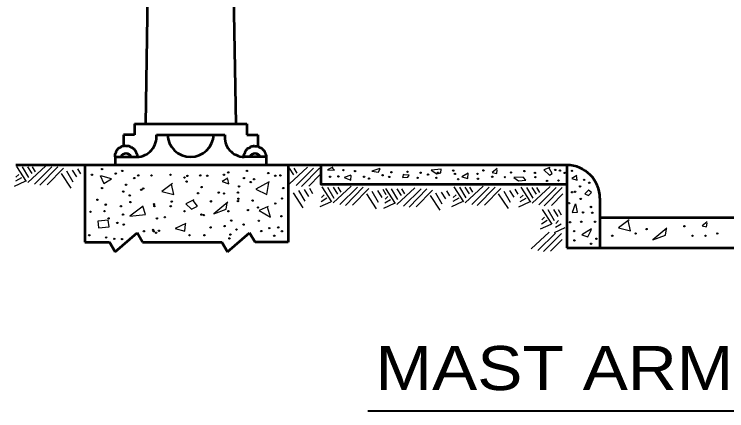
# Model space of a CAD drawing. Extents: x -370 to 486, y -203 to 341.
# Drawn here: x -36.8 to 40.8, y 133.8 to 177 of the extents above; entities that cross this region are included whole.
import ezdxf
from ezdxf.enums import TextEntityAlignment as Align

# ---------------------------------------------------------------- set-up
doc = ezdxf.new("R2010")
doc.units = 0
doc.header["$LTSCALE"] = 0.96
doc.layers.add('1', color=7, linetype='Continuous', lineweight=53)

msp = doc.modelspace()

# ---------------------------------------------------------------- hatches: boundary and pattern name
at = {"layer": '1'}
for points in [[(-27.1974, 160.0917, 1), (-27.3438, 160.0917, 1)], [(-24.9998, 159.8848, 1), (-25.1462, 159.8848, 1)], [(-11.4259, 159.8848, 1), (-11.5723, 159.8848, 1)], [(-0.9302, 159.9722, 1), (-1.0766, 159.9722, 1)], [(0.3404, 159.8705, 1), (0.194, 159.8705, 1)], [(6.058, 159.7943, 1), (5.9116, 159.7943, 1)], [(11.0387, 159.9214, 1), (10.8923, 159.9214, 1)], [(14.3167, 159.9468, 1), (14.1703, 159.9468, 1)], [(18.7892, 159.8705, 1), (18.6428, 159.8705, 1)], [(22.1435, 159.9976, 1), (21.9971, 159.9976, 1)], [(22.6517, 159.9214, 1), (22.5053, 159.9214, 1)], [(23.9764, 159.898, 1), (23.83, 159.898, 1)], [(-28.3092, 159.4709, 1), (-28.4556, 159.4709, 1)], [(-25.7237, 159.6003, 1), (-25.8701, 159.6003, 1)], [(-23.707, 159.1089, 1), (-23.8534, 159.1089, 1)], [(-23.2675, 159.3934, 1), (-23.4139, 159.3934, 1)], [(-21.8196, 159.3934, 1), (-21.966, 159.3934, 1)], [(-19.7512, 159.4709, 1), (-19.8976, 159.4709, 1)], [(-18.2257, 159.1606, 1), (-18.3721, 159.1606, 1)], [(-17.9155, 159.3416, 1), (-18.0619, 159.3416, 1)], [(-16.5193, 159.3934, 1), (-16.6657, 159.3934, 1)], [(-15.7437, 159.3675, 1), (-15.8901, 159.3675, 1)], [(-13.9338, 159.4709, 1), (-14.0802, 159.4709, 1)], [(-13.4684, 159.7296, 1), (-13.6148, 159.7296, 1)], [(-11.762, 159.1089, 1), (-11.9084, 159.1089, 1)], [(-9.0989, 159.652, 1), (-9.2453, 159.652, 1)], [(-8.3491, 159.3675, 1), (-8.4955, 159.3675, 1)], [(-7.7803, 159.3934, 1), (-7.9267, 159.3934, 1)], [(-2.3786, 159.2605, 1), (-2.525, 159.2605, 1)], [(-1.4638, 159.2859, 1), (-1.6102, 159.2859, 1)], [(1.3315, 159.2605, 1), (1.1851, 159.2605, 1)], [(1.8651, 159.0571, 1), (1.7187, 159.0571, 1)], [(3.339, 159.413, 1), (3.1926, 159.413, 1)], [(4.0759, 159.235, 1), (3.9295, 159.235, 1)], [(4.3046, 159.7434, 1), (4.1582, 159.7434, 1)], [(7.1507, 159.1334, 1), (7.0043, 159.1334, 1)], [(7.481, 159.6926, 1), (7.3346, 159.6926, 1)], [(8.2942, 159.4892, 1), (8.1478, 159.4892, 1)], [(9.209, 159.1334, 1), (9.0626, 159.1334, 1)], [(9.3869, 159.6926, 1), (9.2405, 159.6926, 1)], [(11.2165, 159.5655, 1), (11.0701, 159.5655, 1)], [(13.6815, 159.5655, 1), (13.5351, 159.5655, 1)], [(13.7323, 159.0317, 1), (13.5859, 159.0317, 1)], [(15.2824, 159.2605, 1), (15.136, 159.2605, 1)], [(16.6546, 159.2096, 1), (16.5082, 159.2096, 1)], [(17.3153, 159.718, 1), (17.1689, 159.718, 1)], [(19.9327, 159.6672, 1), (19.7863, 159.6672, 1)], [(19.9835, 159.2096, 1), (19.8371, 159.2096, 1)], [(23.1854, 159.6672, 1), (23.039, 159.6672, 1)], [(-24.5861, 158.3847, 1), (-24.7325, 158.3847, 1)], [(-17.993, 158.7209, 1), (-18.1394, 158.7209, 1)], [(-11.0122, 158.6692, 1), (-11.1586, 158.6692, 1)], [(-10.6502, 158.9795, 1), (-10.7966, 158.9795, 1)], [(11.5723, 158.9808, 1), (11.4259, 158.9808, 1)], [(21.2541, 158.8029, 1), (21.1077, 158.8029, 1)], [(22.4992, 158.8283, 1), (22.3528, 158.8283, 1)], [(25.2948, 158.9089, 1), (25.1484, 158.9089, 1)], [(25.8551, 158.5957, 1), (25.7087, 158.5957, 1)], [(-27.1974, 158.0226, 1), (-27.3438, 158.0226, 1)], [(-24.8963, 157.6347, 1), (-25.0427, 157.6347, 1)], [(-22.9314, 157.8416, 1), (-23.0778, 157.8416, 1)], [(-22.7245, 157.9709, 1), (-22.8709, 157.9709, 1)], [(-16.752, 157.4536, 1), (-16.8984, 157.4536, 1)], [(-16.3642, 158.1261, 1), (-16.5106, 158.1261, 1)], [(-14.5026, 157.5312, 1), (-14.649, 157.5312, 1)], [(-12.4084, 157.5312, 1), (-12.5548, 157.5312, 1)], [(-12.2791, 158.2036, 1), (-12.4255, 158.2036, 1)], [(-7.4701, 158.0226, 1), (-7.6165, 158.0226, 1)], [(23.9764, 157.5571, 1), (23.83, 157.5571, 1)], [(24.306, 157.6231, 1), (24.1596, 157.6231, 1)], [(24.8498, 158.2, 1), (24.7034, 158.2, 1)], [(-27.7145, 156.7553, 1), (-27.8609, 156.7553, 1)], [(-24.1983, 157.2208, 1), (-24.3447, 157.2208, 1)], [(-13.9338, 157.4277, 1), (-14.0802, 157.4277, 1)], [(-12.3567, 156.8588, 1), (-12.5031, 156.8588, 1)], [(-7.6252, 156.8846, 1), (-7.7716, 156.8846, 1)], [(24.9158, 156.8318, 1), (24.7694, 156.8318, 1)], [(-26.8096, 156.2122, 1), (-26.956, 156.2122, 1)], [(-25.1549, 156.0311, 1), (-25.3013, 156.0311, 1)], [(-24.1207, 156.4967, 1), (-24.2671, 156.4967, 1)], [(-21.561, 156.2639, 1), (-21.7074, 156.2639, 1)], [(-21.5093, 156.057, 1), (-21.6557, 156.057, 1)], [(-19.7253, 156.0311, 1), (-19.8717, 156.0311, 1)], [(-19.6219, 156.5484, 1), (-19.7683, 156.5484, 1)], [(-15.3558, 156.5743, 1), (-15.5022, 156.5743, 1)], [(-12.4084, 156.6001, 1), (-12.5548, 156.6001, 1)], [(-10.8054, 156.6518, 1), (-10.9518, 156.6518, 1)], [(-10.2107, 155.9018, 1), (-10.3571, 155.9018, 1)], [(-8.3491, 156.3415, 1), (-8.4955, 156.3415, 1)], [(23.6633, 156.3702, 1), (23.5169, 156.3702, 1)], [(26.0364, 155.958, 1), (25.89, 155.958, 1)], [(-28.4643, 155.4363, 1), (-28.6107, 155.4363, 1)], [(-26.9389, 155.5139, 1), (-27.0853, 155.5139, 1)], [(-24.9222, 155.1259, 1), (-25.0686, 155.1259, 1)], [(-18.2257, 155.488, 1), (-18.3721, 155.488, 1)], [(-16.39, 155.1259, 1), (-16.5364, 155.1259, 1)], [(-13.4426, 155.488, 1), (-13.589, 155.488, 1)], [(-11.3225, 155.6173, 1), (-11.4689, 155.6173, 1)], [(25.1794, 155.3646, 1), (25.033, 155.3646, 1)], [(26.1847, 155.3316, 1), (26.0383, 155.3316, 1)], [(-26.4993, 154.7121, 1), (-26.6457, 154.7121, 1)], [(-21.2249, 154.7121, 1), (-21.3713, 154.7121, 1)], [(-20.3717, 154.8414, 1), (-20.5181, 154.8414, 1)], [(-16.1315, 155.0742, 1), (-16.2779, 155.0742, 1)], [(-13.1323, 154.4793, 1), (-13.2787, 154.4793, 1)], [(-10.1331, 154.4535, 1), (-10.2795, 154.4535, 1)], [(-7.6769, 154.9449, 1), (-7.8233, 154.9449, 1)], [(24.9817, 154.359, 1), (24.8353, 154.359, 1)], [(26.4813, 154.359, 1), (26.3349, 154.359, 1)], [(-25.5427, 154.2207, 1), (-25.6891, 154.2207, 1)], [(-24.8446, 154.0397, 1), (-24.991, 154.0397, 1)], [(-15.3817, 153.7293, 1), (-15.5281, 153.7293, 1)], [(-13.8562, 153.8845, 1), (-14.0026, 153.8845, 1)], [(-11.7878, 154.0397, 1), (-11.9342, 154.0397, 1)], [(-8.9955, 153.6517, 1), (-9.1419, 153.6517, 1)], [(-8.013, 153.7293, 1), (-8.1594, 153.7293, 1)], [(23.7622, 154.293, 1), (23.6158, 154.293, 1)], [(36.2199, 153.8654, 1), (36.0735, 153.8654, 1)], [(-28.5936, 152.8758, 1), (-28.74, 152.8758, 1)], [(-22.647, 153.3155, 1), (-22.7934, 153.3155, 1)], [(-21.6645, 153.4707, 1), (-21.8109, 153.4707, 1)], [(-21.5869, 153.3155, 1), (-21.7333, 153.3155, 1)], [(-21.3283, 153.1603, 1), (-21.4747, 153.1603, 1)], [(-21.0181, 153.3672, 1), (-21.1645, 153.3672, 1)], [(-17.6828, 152.8758, 1), (-17.8292, 152.8758, 1)], [(-16.0539, 152.8758, 1), (-16.2003, 152.8758, 1)], [(-13.2357, 152.9534, 1), (-13.3821, 152.9534, 1)], [(-12.5635, 153.4965, 1), (-12.7099, 153.4965, 1)], [(-9.8746, 153.3413, 1), (-10.021, 153.3413, 1)], [(-8.4525, 152.8241, 1), (-8.5989, 152.8241, 1)], [(-7.6252, 153.3155, 1), (-7.7716, 153.3155, 1)], [(24.2071, 153.3369, 1), (24.0607, 153.3369, 1)], [(28.3602, 152.833, 1), (28.2138, 152.833, 1)], [(30.9008, 153.0713, 1), (30.7544, 153.0713, 1)], [(32.0916, 153.5478, 1), (31.9452, 153.5478, 1)], [(37.0932, 152.833, 1), (36.9468, 152.833, 1)], [(38.5129, 152.833, 1), (38.3665, 152.833, 1)], [(39.7925, 153.0713, 1), (39.6461, 153.0713, 1)], [(-26.7579, 152.643, 1), (-26.9043, 152.643, 1)], [(-25.8788, 152.4879, 1), (-26.0252, 152.4879, 1)], [(-25.0256, 152.462, 1), (-25.172, 152.462, 1)], [(-13.3391, 152.5396, 1), (-13.4855, 152.5396, 1)], [(24.2401, 152.3148, 1), (24.0937, 152.3148, 1)], [(26.6297, 152.4962, 1), (26.4833, 152.4962, 1)], [(26.0529, 151.9521, 1), (25.9065, 151.9521, 1)]]:
    msp.add_hatch(color=256, dxfattribs=at).paths.add_polyline_path(points)

# ---------------------------------------------------------------- linework, layer by layer
for p, q in [((-20.3421, 292.1994), (-22.562, 165.0188)), ((-14.6437, 275.1007), (-12.7222, 165.0188)), ((-23.762, 165.0188), (-11.5222, 165.0188)), ((-23.762, 165.0188), (-23.762, 163.8188)), ((-11.5222, 165.0188), (-11.5222, 163.8188)), ((-23.762, 163.8188), (-24.962, 163.8188)), ((-24.962, 163.8188), (-24.962, 162.6188)), ((-21.362, 163.8188), (-13.9222, 163.8188)), ((-11.5222, 163.8188), (-10.3222, 163.8188)), ((-10.3222, 163.8188), (-10.3222, 162.572)), ((-25.862, 161.4188), (-25.862, 160.5188)), ((-25.862, 161.4188), (-23.462, 161.4188)), ((-9.4222, 161.4188), (-11.8222, 161.4188)), ((-9.4222, 161.4188), (-9.4222, 160.5188)), ((23.338, 160.5188), (-36.662, 160.5188)), ((-29.162, 160.5188), (-29.162, 152.1188)), ((-7.0222, 160.5188), (-7.0222, 152.1188)), ((23.338, 160.5188), (23.338, 151.5188)), ((26.938, 156.9188), (26.938, 151.5188)), ((26.938, 154.8188), (116.938, 154.8188)), ((-25.862, 151.0796), (-23.462, 153.158)), ((-22.862, 152.1188), (-23.462, 153.158)), ((-13.6222, 151.0796), (-11.2222, 153.158)), ((-10.6222, 152.1188), (-11.2222, 153.158)), ((-29.162, 152.1188), (-26.462, 152.1188)), ((-25.862, 151.0796), (-26.462, 152.1188)), ((-22.862, 152.1188), (-14.2222, 152.1188)), ((-13.6222, 151.0796), (-14.2222, 152.1188)), ((-7.0222, 152.1188), (-10.6222, 152.1188)), ((23.338, 151.5188), (116.938, 151.5188))]:
    msp.add_line(p, q, dxfattribs=at)
at = {"layer": '1', "lineweight": 25}
for p, q in [((-36.6059, 160.368), (-35.5512, 158.7491)), ((-35.9876, 160.3498), (-35.2966, 159.1674)), ((-35.3875, 160.3498), (-34.9147, 159.604)), ((-35.3693, 158.6399), (-33.4054, 160.459)), ((-34.8783, 160.3498), (-34.551, 159.7859)), ((-34.6419, 158.458), (-32.7326, 160.3498)), ((-34.0418, 158.3489), (-32.0961, 160.3316)), ((-33.2599, 158.3852), (-31.496, 160.1861)), ((-31.1687, 159.895), (-30.4777, 158.7126)), ((-30.5504, 159.986), (-30.0776, 159.2402)), ((-29.9685, 160.1316), (-29.6412, 159.5677)), ((-6.8905, 160.2058), (-6.4177, 159.46)), ((-6.8723, 158.4959), (-4.9084, 160.315)), ((-6.3813, 160.2058), (-6.054, 159.6419)), ((-6.1449, 158.314), (-4.2356, 160.2058)), ((-5.5448, 158.2049), (-3.5991, 160.1876)), ((-36.0603, 159.1492), (-36.6968, 158.7672)), ((-36.3513, 159.5131), (-36.6604, 159.222)), ((-31.7506, 159.6222), (-30.6959, 158.0033)), ((-4.7629, 158.2412), (-3.5783, 159.4506)), ((-35.6784, 158.7309), (-36.8423, 158.2033)), ((-5.875, 157.7657), (-5.184, 156.5833)), ((-5.2567, 157.8567), (-4.7839, 157.1109)), ((-4.6748, 158.0023), (-4.3475, 157.4384)), ((-3.3432, 158.1374), (-2.2885, 156.5185)), ((-2.7249, 158.1192), (-2.0339, 156.9368)), ((-2.1248, 158.1192), (-1.652, 157.3734)), ((-2.1066, 156.4093), (-0.1427, 158.2284)), ((-1.6156, 158.1192), (-1.2883, 157.5553)), ((-1.3792, 156.2274), (0.5301, 158.1192)), ((-0.7791, 156.1183), (1.1666, 158.101)), ((0.0028, 156.1546), (1.7667, 157.9555)), ((2.094, 157.6644), (2.785, 156.482)), ((2.7123, 157.7554), (3.1851, 157.0096)), ((3.2942, 157.901), (3.6215, 157.3371)), ((3.5912, 157.9716), (4.6459, 156.3527)), ((4.2095, 157.9534), (4.9005, 156.771)), ((4.8096, 157.9534), (5.2824, 157.2076)), ((4.8278, 156.2435), (6.7917, 158.0626)), ((5.3188, 157.9534), (5.6461, 157.3895)), ((5.5552, 156.0616), (7.4645, 157.9534)), ((6.1553, 155.9525), (8.101, 157.9352)), ((6.9372, 155.9888), (8.7011, 157.7897)), ((9.6467, 157.5896), (10.1195, 156.8438)), ((10.2286, 157.7352), (10.5559, 157.1713)), ((11.0207, 158.1497), (12.0754, 156.5308)), ((11.639, 158.1315), (12.33, 156.9491)), ((12.2391, 158.1315), (12.7119, 157.3857)), ((12.2573, 156.4216), (14.2212, 158.2407)), ((12.7483, 158.1315), (13.0756, 157.5676)), ((12.9847, 156.2397), (14.894, 158.1315)), ((13.5848, 156.1306), (15.5305, 158.1133)), ((14.3667, 156.1669), (16.1306, 157.9678)), ((16.4579, 157.6767), (17.1489, 156.4943)), ((17.0762, 157.7677), (17.549, 157.0219)), ((17.6581, 157.9133), (17.9854, 157.3494)), ((18.3167, 158.1052), (19.3714, 156.4863)), ((18.935, 158.087), (19.626, 156.9046)), ((19.5351, 158.087), (20.0079, 157.3412)), ((19.5533, 156.3771), (21.5172, 158.1962)), ((20.0443, 158.087), (20.3716, 157.5231)), ((20.2807, 156.1952), (22.19, 158.087)), ((20.8808, 156.0861), (22.8265, 158.0688)), ((-6.4569, 157.4929), (-5.4022, 155.874)), ((-2.7976, 156.9186), (-3.4341, 156.5366)), ((-3.0886, 157.2825), (-3.3977, 156.9914)), ((1.5121, 157.3916), (2.5668, 155.7727)), ((4.1368, 156.7528), (3.5003, 156.3708)), ((3.8458, 157.1167), (3.5367, 156.8256)), ((8.4465, 157.2258), (9.5012, 155.6069)), ((9.0284, 157.4986), (9.7194, 156.3162)), ((11.5663, 156.9309), (10.9298, 156.5489)), ((11.2753, 157.2948), (10.9662, 157.0037)), ((15.876, 157.4039), (16.9307, 155.785)), ((18.8623, 156.8864), (18.2258, 156.5044)), ((18.5713, 157.2503), (18.2622, 156.9592)), ((21.6627, 156.1224), (22.9087, 157.3946)), ((-2.4157, 156.5003), (-3.5796, 155.9727)), ((4.5187, 156.3345), (3.3548, 155.8069)), ((11.9482, 156.5126), (10.7843, 155.985)), ((19.2442, 156.4681), (18.0803, 155.9405)), ((20.6523, 155.7022), (21.707, 154.0833)), ((21.2706, 155.684), (21.9616, 154.5016)), ((21.8707, 155.684), (22.3435, 154.9382)), ((22.3799, 155.684), (22.7072, 155.1201)), ((21.1979, 154.4834), (20.5614, 154.1014)), ((20.9069, 154.8473), (20.5978, 154.5562)), ((22.4418, 154.4689), (22.1327, 154.1778)), ((21.5798, 154.0651), (20.4159, 153.5375)), ((23.1147, 153.6867), (21.9508, 153.1591)), ((22.7328, 154.105), (22.0963, 153.723)), ((19.4643, 151.3929), (21.4282, 153.212)), ((20.1917, 151.211), (22.101, 153.1028)), ((20.7918, 151.1019), (22.7375, 153.0846)), ((21.5737, 151.1382), (22.8197, 152.4104))]:
    msp.add_line(p, q, dxfattribs=at)
at = {"layer": '1', "lineweight": 40}
msp.add_line((1.6765, 133.7613), (75.9021, 133.7613), dxfattribs=at)
at = {"layer": '1'}
msp.add_lwpolyline([(23.338, 158.4188), (-3.4222, 158.4188), (-3.4222, 160.5188)], dxfattribs=at)
at = {"layer": '1', "lineweight": 25}
for points in [[(-2.1419, 160.294), (-2.736, 160.0097), (-1.961, 159.9839), (-2.2194, 160.2164)], [(2.973, 160.1648), (2.0947, 159.8547), (2.818, 159.7513), (2.9989, 160.1389)], [(9.6379, 160.0872), (8.5529, 159.958), (9.1729, 159.5704), (9.6121, 159.6738), (9.6637, 160.0614)], [(15.7603, 160.1389), (15.2178, 159.7255), (15.7086, 159.5963), (15.7603, 160.0097)], [(21.4693, 160.2681), (20.8235, 160.0097), (21.4435, 159.4154), (21.7535, 159.5963), (21.4176, 160.1906)], [(-27.4774, 159.3934), (-27.0896, 158.514), (-26.2622, 159.0313), (-27.3999, 159.3417)], [(-13.5933, 159.1089), (-14.2138, 158.7468), (-13.4899, 158.4882), (-13.5674, 158.9796)], [(-0.2044, 159.4412), (-0.9019, 159.1828), (-0.1786, 158.8986), (-0.1527, 159.3895)], [(5.5305, 159.5187), (5.4272, 159.1828), (6.0213, 159.2086), (6.1505, 159.4412), (5.5046, 159.4671)], [(12.6087, 159.6479), (11.9112, 159.2345), (12.557, 159.0536), (12.5828, 159.6479)], [(18.6019, 159.2086), (17.5686, 159.1828), (18.0852, 158.7952), (18.8602, 158.8986), (18.6277, 159.157)], [(24.4084, 159.4052), (23.881, 159.0755), (24.4743, 158.8942), (24.3919, 159.3722)], [(-19.6175, 158.514), (-20.781, 157.6606), (-19.4624, 157.3243), (-19.7209, 158.4365)], [(-9.0686, 158.6951), (-10.5165, 157.8933), (-9.3272, 157.3243), (-9.1204, 158.6175)], [(25.7432, 157.8391), (25.2818, 157.394), (25.7103, 157.1962), (26.0399, 157.5424), (25.7103, 157.8061)], [(-22.7977, 156.057), (-24.2455, 154.9449), (-22.5391, 155.1518), (-22.8494, 156.0312)], [(-17.2905, 156.7295), (-18.1696, 156.2898), (-17.5232, 155.7208), (-16.9027, 156.057), (-17.3681, 156.6777)], [(-13.5933, 156.4967), (-15.1187, 155.2035), (-13.7484, 155.7208), (-13.645, 156.3933)], [(-9.1721, 156.0053), (-10.1804, 155.5915), (-8.9394, 154.8415), (-9.2755, 155.9277)], [(24.2436, 156.273), (23.9305, 155.3663), (24.4908, 155.3828), (24.326, 156.2895)], [(-27.736, 154.4535), (-27.6843, 153.6776), (-26.4949, 153.8069), (-26.6242, 154.5052), (-27.7101, 154.4018)], [(30.1169, 154.5509), (28.9534, 153.6975), (30.272, 153.3612), (30.0135, 154.4734)], [(-18.1438, 154.1431), (-19.3331, 153.6259), (-18.2472, 153.3414), (-18.1955, 154.0914)], [(34.2309, 153.666), (32.7055, 152.3728), (34.0758, 152.8901), (34.1792, 153.5626)], [(38.6112, 154.3359), (38.0687, 153.9225), (38.5595, 153.7933), (38.6112, 154.2067)], [(26.0234, 153.5859), (24.9852, 152.9265), (25.6114, 152.6957), (26.0069, 153.52)]]:
    msp.add_lwpolyline(points, dxfattribs=at)
for centre in [(-27.2706, 160.0917), (-25.073, 159.8848), (-11.4991, 159.8848), (-1.0034, 159.9722), (0.2672, 159.8705), (5.9848, 159.7943), (10.9655, 159.9214), (14.2435, 159.9468), (18.716, 159.8705), (22.0703, 159.9976), (22.5785, 159.9214), (23.9032, 159.898), (-28.3824, 159.4709), (-25.7969, 159.6003), (-23.7802, 159.1089), (-23.3407, 159.3934), (-21.8928, 159.3934), (-19.8244, 159.4709), (-18.2989, 159.1606), (-17.9887, 159.3416), (-16.5925, 159.3934), (-15.8169, 159.3675), (-14.007, 159.4709), (-13.5416, 159.7296), (-11.8352, 159.1089), (-9.1721, 159.652), (-8.4223, 159.3675), (-7.8535, 159.3934), (-2.4518, 159.2605), (-1.537, 159.2859), (1.2583, 159.2605), (1.7919, 159.0571), (3.2658, 159.413), (4.0027, 159.235), (4.2314, 159.7434), (7.0775, 159.1334), (7.4078, 159.6926), (8.221, 159.4892), (9.1358, 159.1334), (9.3137, 159.6926), (11.1433, 159.5655), (13.6083, 159.5655), (13.6591, 159.0317), (15.2092, 159.2605), (16.5814, 159.2096), (17.2421, 159.718), (19.8595, 159.6672), (19.9103, 159.2096), (23.1122, 159.6672), (-24.6593, 158.3847), (-18.0662, 158.7209), (-11.0854, 158.6692), (-10.7234, 158.9795), (11.4991, 158.9808), (21.1809, 158.8029), (22.426, 158.8283), (25.2216, 158.9089), (25.7819, 158.5957), (-27.2706, 158.0226), (-24.9695, 157.6347), (-23.0046, 157.8416), (-22.7977, 157.9709), (-16.8252, 157.4536), (-16.4374, 158.1261), (-14.5758, 157.5312), (-12.4816, 157.5312), (-12.3523, 158.2036), (-7.5433, 158.0226), (23.9032, 157.5571), (24.2328, 157.6231), (24.7766, 158.2), (-27.7877, 156.7553), (-24.2715, 157.2208), (-14.007, 157.4277), (-12.4299, 156.8588), (-7.6984, 156.8846), (24.8426, 156.8318), (-26.8828, 156.2122), (-25.2281, 156.0311), (-24.1939, 156.4967), (-21.6342, 156.2639), (-21.5825, 156.057), (-19.7985, 156.0311), (-19.6951, 156.5484), (-15.429, 156.5743), (-12.4816, 156.6001), (-10.8786, 156.6518), (-10.2839, 155.9018), (-8.4223, 156.3415), (23.5901, 156.3702), (25.9632, 155.958), (-28.5375, 155.4363), (-27.0121, 155.5139), (-24.9954, 155.1259), (-18.2989, 155.488), (-16.4632, 155.1259), (-13.5158, 155.488), (-11.3957, 155.6173), (25.1062, 155.3646), (26.1115, 155.3316), (-26.5725, 154.7121), (-21.2981, 154.7121), (-20.4449, 154.8414), (-16.2047, 155.0742), (-13.2055, 154.4793), (-10.2063, 154.4535), (-7.7501, 154.9449), (24.9085, 154.359), (26.4081, 154.359), (-25.6159, 154.2207), (-24.9178, 154.0397), (-15.4549, 153.7293), (-13.9294, 153.8845), (-11.861, 154.0397), (-9.0687, 153.6517), (-8.0862, 153.7293), (23.689, 154.293), (36.1467, 153.8654), (-28.6668, 152.8758), (-22.7202, 153.3155), (-21.7377, 153.4707), (-21.6601, 153.3155), (-21.4015, 153.1603), (-21.0913, 153.3672), (-17.756, 152.8758), (-16.1271, 152.8758), (-13.3089, 152.9534), (-12.6367, 153.4965), (-9.9478, 153.3413), (-8.5257, 152.8241), (-7.6984, 153.3155), (24.1339, 153.3369), (28.287, 152.833), (30.8276, 153.0713), (32.0184, 153.5478), (37.02, 152.833), (38.4397, 152.833), (39.7193, 153.0713), (-26.8311, 152.643), (-25.952, 152.4879), (-25.0988, 152.462), (-13.4123, 152.5396), (24.1669, 152.3148), (26.5565, 152.4962), (25.9797, 151.9521)]:
    msp.add_circle(centre, 0.0732, dxfattribs=at)
at = {"layer": '1'}
for centre, radius, start, end in [((-23.513, 163.5822), 2.164, 271.35033, 6.27782), ((-17.6421, 163.9417), 2.5229, 182.79209, 357.20791), ((-11.7626, 163.5822), 2.164, 173.72218, 268.64967), ((-24.662, 161.0941), 0.6822, 28.42043, 151.57958), ((-10.6222, 161.0941), 0.6822, 28.42043, 151.57958), ((23.338, 156.9188), 3.6, 0, 90)]:
    msp.add_arc(centre, radius, start, end, dxfattribs=at)
for points in [[(-25.862, 161.4188), (-25.8671, 161.5619), (-25.8551, 161.7219), (-25.8231, 161.7779), (-25.7831, 161.838), (-25.7391, 161.906), (-25.7311, 161.954), (-25.7191, 162.026), (-25.7071, 162.0621), (-25.675, 162.1141), (-25.643, 162.1781), (-25.595, 162.2341), (-25.539, 162.3022), (-25.515, 162.3542), (-25.487, 162.3862), (-25.423, 162.4062), (-25.335, 162.4262), (-25.275, 162.4582), (-25.195, 162.4942), (-25.155, 162.5423), (-25.083, 162.5943), (-25.019, 162.6383), (-24.962, 162.6188), (-24.811, 162.6543), (-24.6909, 162.6383), (-24.5989, 162.6263), (-24.5709, 162.6263), (-24.4949, 162.6263), (-24.4629, 162.6303), (-24.4269, 162.6223), (-24.3109, 162.5983), (-24.2629, 162.5503), (-24.1429, 162.4942), (-24.1029, 162.4702), (-24.0029, 162.4382), (-23.9629, 162.4182), (-23.9109, 162.3622), (-23.8469, 162.3182), (-23.8229, 162.2741), (-23.7628, 162.2101), (-23.7188, 162.1661), (-23.6868, 162.1381), (-23.6468, 162.0901), (-23.6228, 162.022), (-23.6028, 161.934), (-23.5748, 161.894), (-23.5268, 161.7859), (-23.4948, 161.7299), (-23.4588, 161.6419), (-23.4548, 161.5739), (-23.4708, 161.4818), (-23.462, 161.4188)], [(-11.8183, 161.4185), (-11.822, 161.5237), (-11.81, 161.6837), (-11.778, 161.7397), (-11.738, 161.7998), (-11.694, 161.8678), (-11.686, 161.9158), (-11.674, 161.9878), (-11.662, 162.0239), (-11.6299, 162.0759), (-11.5979, 162.1399), (-11.5499, 162.1959), (-11.4939, 162.264), (-11.4699, 162.316), (-11.4419, 162.348), (-11.3779, 162.368), (-11.2899, 162.388), (-11.2299, 162.42), (-11.1499, 162.456), (-11.1099, 162.5041), (-11.0379, 162.5561), (-10.9739, 162.6001), (-10.9169, 162.5806), (-10.7659, 162.6161), (-10.6458, 162.6001), (-10.5538, 162.5881), (-10.5258, 162.5881), (-10.4498, 162.5881), (-10.4178, 162.5921), (-10.3818, 162.5841), (-10.2658, 162.5601), (-10.2178, 162.5121), (-10.0978, 162.456), (-10.0578, 162.432), (-9.9578, 162.4), (-9.9178, 162.38), (-9.8658, 162.324), (-9.8018, 162.28), (-9.7778, 162.2359), (-9.7177, 162.1719), (-9.6737, 162.1279), (-9.6417, 162.0999), (-9.6017, 162.0519), (-9.5777, 161.9838), (-9.5577, 161.8958), (-9.5297, 161.8558), (-9.4817, 161.7477), (-9.4497, 161.6917), (-9.4137, 161.6037), (-9.4097, 161.5357), (-9.4257, 161.4436), (-9.4223, 161.4191)]]:
    msp.add_spline(points, degree=3, dxfattribs=at)

# ---------------------------------------------------------------- texts
at = {"layer": '1', "width": 1.15}
msp.add_text('MAST ARM METHOD', height=4.8, dxfattribs=at).set_placement((39.0059, 136.0141), align=Align.CENTER)

doc.saveas('drawing.dxf')
